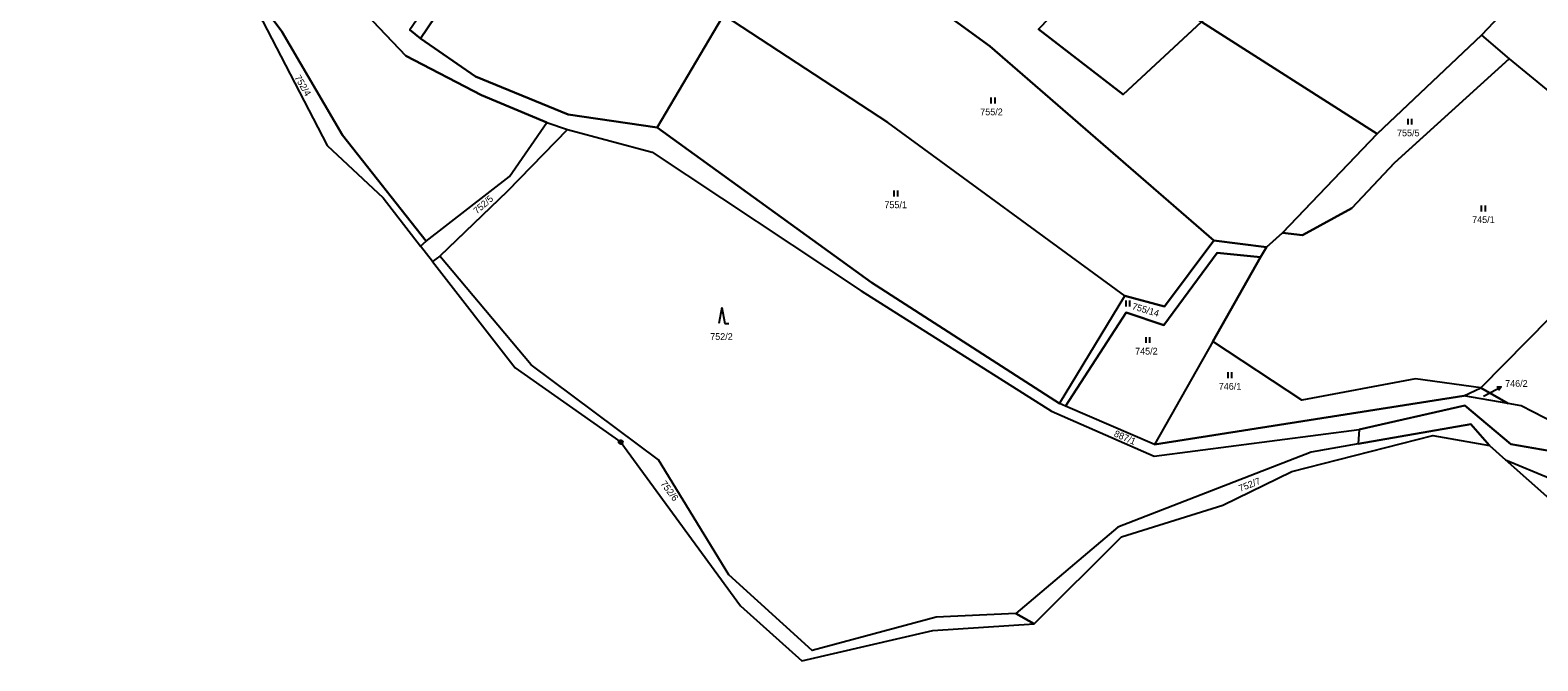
# Model space of a CAD drawing. Extents: x -654083 to -650132, y -1099819 to -1096699.
# Drawn here: x -653842.2 to -653461.9, y -1098390.2 to -1098231 of the extents above; entities that cross this region are included whole.
import ezdxf

# ---------------------------------------------------------------- set-up
doc = ezdxf.new("R2010")
doc.units = 0
for name, color, linetype in [('Geodetické body', 7, 'Continuous'), ('Obvody jako plochy', 7, 'Continuous'), ('Parcelní čísla', 7, 'Continuous'), ('Prvky pro prodl_ par_ č_', 7, 'Continuous'), ('Značky kultur', 7, 'Continuous')]:
    doc.layers.add(name, color=color, linetype=linetype)

msp = doc.modelspace()

# ---------------------------------------------------------------- linework, layer by layer
at = {"layer": 'Geodetické body'}
for radius in [0.5, 0.001]:
    msp.add_circle((-653693.18, -1098334.96), radius, dxfattribs=at)
at = {"layer": 'Obvody jako plochy'}
for points in [[(-653618.97, -1098056.31), (-653635.8, -1098078.5), (-653648.49, -1098094.45), (-653669.6, -1098121.79), (-653680.58, -1098136.79), (-653690.76, -1098150.69), (-653709.18, -1098175.93), (-653718.33, -1098190.03), (-653746.37, -1098230.94), (-653743.73, -1098233.12), (-653714.84, -1098190.36), (-653706.96, -1098178.69), (-653704.43, -1098174.89), (-653672.35, -1098130.56), (-653648.86, -1098101.05), (-653625.26, -1098070.79), (-653607.11, -1098043.87), (-653598.42, -1098044.74), (-653607.69, -1098040.36)], [(-653721.27, -1098267.91), (-653711.82, -1098254.28), (-653728.34, -1098247.4), (-653747.42, -1098237.45), (-653784.16, -1098198.82), (-653817.94, -1098151.09), (-653828.49, -1098119.16), (-653842.18, -1098131.36), (-653833.25, -1098153.1), (-653825.81, -1098167.82), (-653778.72, -1098231.33), (-653763.42, -1098257.49), (-653742.27, -1098284.25)], [(-653827.67, -1098166.73), (-653783.54, -1098228.67), (-653767.24, -1098260.09), (-653753.1, -1098273.36), (-653743.69, -1098285.49), (-653742.27, -1098284.25), (-653763.42, -1098257.49), (-653778.72, -1098231.33), (-653825.81, -1098167.82), (-653833.25, -1098153.1)], [(-653546.7, -1098228.92), (-653502.41, -1098257.19), (-653526.27, -1098282.15), (-653530.29, -1098285.81), (-653543.55, -1098284.07), (-653600.1, -1098235.04), (-653647.07, -1098200.83), (-653629.2, -1098174.91), (-653596.62, -1098197.26), (-653571.22, -1098213.59), (-653587.81, -1098230.74), (-653566.43, -1098247.25)], [(-653667.58, -1098227.83), (-653714.84, -1098190.36), (-653743.73, -1098233.12), (-653729.84, -1098242.69), (-653706.46, -1098252.31), (-653684.02, -1098255.61)], [(-653510.59, -1098197.1), (-653468.56, -1098224.39), (-653476.06, -1098232.31), (-653502.41, -1098257.19), (-653546.7, -1098228.92)], [(-653556.04, -1098300.72), (-653566.03, -1098298.04), (-653625.84, -1098254.28), (-653667.18, -1098227.19), (-653659.63, -1098215.26), (-653657.02, -1098211.29), (-653647.07, -1098200.83), (-653600.1, -1098235.04), (-653543.55, -1098284.07)], [(-653571.22, -1098213.59), (-653546.7, -1098228.92), (-653566.43, -1098247.25), (-653587.81, -1098230.74)], [(-653629.97, -1098294.65), (-653582.55, -1098325.18), (-653566.03, -1098298.04), (-653625.84, -1098254.28), (-653667.18, -1098227.19), (-653667.58, -1098227.83), (-653684.02, -1098255.61)], [(-653521.22, -1098282.73), (-653526.27, -1098282.15), (-653502.41, -1098257.19), (-653476.06, -1098232.31), (-653469.12, -1098238.28), (-653497.99, -1098264.52), (-653508.81, -1098275.97)], [(-653452.91, -1098297.64), (-653476.22, -1098321.29), (-653492.74, -1098319.03), (-653521.4, -1098324.34), (-653543.83, -1098309.55), (-653531.78, -1098288.3), (-653530.29, -1098285.81), (-653526.27, -1098282.15), (-653521.22, -1098282.73), (-653508.81, -1098275.97), (-653497.99, -1098264.52), (-653469.12, -1098238.28), (-653426.6, -1098273.03)], [(-653711.82, -1098254.28), (-653706.66, -1098256.06), (-653721.77, -1098271.63), (-653738.85, -1098288.03), (-653740.66, -1098289.4), (-653743.69, -1098285.49), (-653742.27, -1098284.25), (-653721.27, -1098267.91)], [(-653685.27, -1098261.76), (-653632.55, -1098296.8), (-653584.55, -1098327.14), (-653558.65, -1098338.51), (-653506.94, -1098331.76), (-653507.15, -1098335.36), (-653519.05, -1098337.54), (-653567.83, -1098356.39), (-653593.53, -1098378.18), (-653613.6, -1098379.14), (-653644.87, -1098387.53), (-653665.93, -1098368.42), (-653683.68, -1098339.47), (-653715.81, -1098315.45), (-653738.85, -1098288.03), (-653721.77, -1098271.63), (-653706.66, -1098256.06)], [(-653428.86, -1098323.02), (-653399.43, -1098340.33), (-653395.28, -1098328.39), (-653388.43, -1098316.97), (-653380.66, -1098318.78), (-653388.17, -1098334.47), (-653391.18, -1098337.36), (-653393.37, -1098339.44), (-653406.24, -1098351.65), (-653448.41, -1098334.89), (-653466.08, -1098325.78), (-653469.31, -1098325.22), (-653476.22, -1098321.29), (-653452.91, -1098297.64), (-653426.6, -1098273.03), (-653419.03, -1098292.84), (-653412.39, -1098301.08)], [(-653531.78, -1098288.3), (-653542.72, -1098287.21), (-653556.17, -1098305.45), (-653565.69, -1098302.28), (-653580.99, -1098325.88), (-653582.55, -1098325.18), (-653566.03, -1098298.04), (-653556.04, -1098300.72), (-653543.55, -1098284.07), (-653530.29, -1098285.81)], [(-653740.66, -1098289.4), (-653719.87, -1098316.19), (-653693.18, -1098334.96), (-653662.97, -1098376.27), (-653647.55, -1098390.16), (-653614.44, -1098382.47), (-653588.9, -1098380.84), (-653593.53, -1098378.18), (-653613.6, -1098379.14), (-653644.87, -1098387.53), (-653665.93, -1098368.42), (-653683.68, -1098339.47), (-653715.81, -1098315.45), (-653738.85, -1098288.03)], [(-653543.83, -1098309.55), (-653558.57, -1098335.58), (-653580.99, -1098325.88), (-653565.69, -1098302.28), (-653556.17, -1098305.45), (-653542.72, -1098287.21), (-653531.78, -1098288.3)], [(-653492.74, -1098319.03), (-653521.4, -1098324.34), (-653543.83, -1098309.55), (-653558.57, -1098335.58), (-653480.49, -1098323.26), (-653476.22, -1098321.29)], [(-653476.22, -1098321.29), (-653469.31, -1098325.22), (-653480.49, -1098323.26)], [(-653474.07, -1098335.78), (-653469.97, -1098339.43), (-653447.33, -1098348.87), (-653458.98, -1098337.19), (-653468.66, -1098335.45), (-653480.23, -1098325.73), (-653506.94, -1098331.76), (-653507.15, -1098335.36), (-653478.77, -1098330.4)], [(-653478.77, -1098330.4), (-653507.15, -1098335.36), (-653519.05, -1098337.54), (-653567.83, -1098356.39), (-653593.53, -1098378.18), (-653588.9, -1098380.84), (-653566.91, -1098358.88), (-653541.34, -1098350.91), (-653523.91, -1098342.35), (-653488.32, -1098333.27), (-653474.07, -1098335.78)], [(-653469.97, -1098339.43), (-653447.33, -1098348.87), (-653442.79, -1098353.02), (-653458.04, -1098350.04)]]:
    msp.add_lwpolyline(points, close=True, dxfattribs=at)
for points in [[(-653784.16, -1098198.82), (-653747.42, -1098237.45), (-653728.34, -1098247.4), (-653711.82, -1098254.28), (-653706.66, -1098256.06), (-653685.27, -1098261.76), (-653632.55, -1098296.8), (-653584.55, -1098327.14), (-653558.65, -1098338.51), (-653506.94, -1098331.76), (-653480.23, -1098325.73), (-653468.66, -1098335.45), (-653458.98, -1098337.19)], [(-653468.56, -1098224.39), (-653476.06, -1098232.31), (-653469.12, -1098238.28), (-653426.6, -1098273.03), (-653419.03, -1098292.84), (-653412.39, -1098301.08), (-653428.86, -1098323.02), (-653399.43, -1098340.33), (-653395.28, -1098328.39), (-653388.43, -1098316.97), (-653380.66, -1098318.78), (-653379.11, -1098315.61), (-653362.81, -1098301.73), (-653367.85, -1098284.07), (-653367.61, -1098264.53), (-653364, -1098241.1), (-653363.54, -1098236.76), (-653384.71, -1098226.25)], [(-653448.41, -1098334.89), (-653466.08, -1098325.78), (-653469.31, -1098325.22), (-653480.49, -1098323.26), (-653558.57, -1098335.58), (-653580.99, -1098325.88), (-653582.55, -1098325.18), (-653629.97, -1098294.65), (-653684.02, -1098255.61), (-653706.46, -1098252.31), (-653729.84, -1098242.69), (-653743.73, -1098233.12), (-653746.37, -1098230.94)]]:
    msp.add_lwpolyline(points, dxfattribs=at)
at = {"layer": 'Prvky pro prodl_ par_ č_'}
for p, q in [((-653475.58, -1098323.35), (-653473.77, -1098322.41)), ((-653473.77, -1098322.41), (-653471.11, -1098321.02))]:
    msp.add_line(p, q, dxfattribs=at)
msp.add_lwpolyline([(-653472.23, -1098321.04), (-653471.11, -1098321.02), (-653471.77, -1098321.93)], dxfattribs=at)
at = {"layer": 'Značky kultur'}
for p, q in [((-653599.8, -1098248.04), (-653599.8, -1098249.54)), ((-653598.78, -1098249.54), (-653598.78, -1098248.04)), ((-653494.68, -1098253.35), (-653494.68, -1098254.85)), ((-653493.66, -1098254.85), (-653493.66, -1098253.35)), ((-653624.34, -1098271.5), (-653624.34, -1098273)), ((-653623.32, -1098273), (-653623.32, -1098271.5)), ((-653476.12, -1098275.24), (-653476.12, -1098276.74)), ((-653475.09, -1098276.74), (-653475.09, -1098275.24)), ((-653565.82, -1098299.27), (-653565.82, -1098300.77)), ((-653564.8, -1098300.77), (-653564.8, -1098299.27)), ((-653667.7, -1098301.01), (-653668.44, -1098305.01)), ((-653667.7, -1098301.01), (-653666.97, -1098305.01)), ((-653666.97, -1098305.01), (-653665.97, -1098305.01)), ((-653560.77, -1098308.44), (-653560.77, -1098309.94)), ((-653559.74, -1098309.94), (-653559.74, -1098308.44)), ((-653540.08, -1098317.3), (-653540.08, -1098318.8)), ((-653539.06, -1098318.8), (-653539.06, -1098317.3))]:
    msp.add_line(p, q, dxfattribs=at)

# ---------------------------------------------------------------- texts
at = {"layer": 'Parcelní čísla'}
for s, height, rotation, p in [('752/4', 1.7, 300.231, (-653775.55, -1098242.94)), ('752/5', 1.7, 40.968, (-653729.48, -1098277.53)), ('755/14', 1.7, 343.836, (-653564.36, -1098301.42)), ('746/2', 0.1, 349.695, (-653475.58, -1098323.35)), ('887/1', 1.7, 336.654, (-653568.95, -1098333.45)), ('752/6', 1.7, 306.864, (-653683.26, -1098345.49)), ('752/7', 1.7, 21.591, (-653536.92, -1098347.53))]:
    msp.add_text(s, height=height, rotation=rotation, dxfattribs=at).set_placement(p)
for s, p in [('755/2', (-653602.52, -1098252.48)), ('755/5', (-653497.38, -1098257.79)), ('755/1', (-653626.69, -1098275.93)), ('745/1', (-653478.43, -1098279.67)), ('752/2', (-653670.63, -1098309.17)), ('745/2', (-653563.45, -1098312.87)), ('746/1', (-653542.35, -1098321.74))]:
    msp.add_text(s, height=1.7, dxfattribs=at).set_placement(p)
at = {"layer": 'Prvky pro prodl_ par_ č_'}
msp.add_text('746/2', height=1.7, dxfattribs=at).set_placement((-653470.11, -1098321.02))

doc.saveas('drawing.dxf')
